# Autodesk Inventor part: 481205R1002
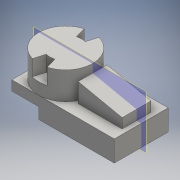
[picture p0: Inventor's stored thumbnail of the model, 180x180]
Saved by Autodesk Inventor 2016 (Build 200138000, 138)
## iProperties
Created: 2018-12
Part Number: 481205R1002
Material: 일반
Document SubType Name: Modeling
Designer: USER
Density: 1 g/cm^3
Appearance: 기본값
Author: USER
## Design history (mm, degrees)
sketch "스케치1"
  geometry: L1 (-78, 41)-(78, 41); L2 (78, 41)-(78, -41); L3 (78, -41)-(-78, -41); L4 (-78, -41)-(-78, 41); L5 (-78, 41)-(78, -41); L6 (78, 41)-(-78, -41); 1 further point
  constraints: 12 end point, 2 midpoint, 2 parallel, 1 horizontal, 1 perpendicular
  dimensions: "d5" = 82 distance of L1.end L2.end; "d6" = 156 distance of L2.end L3.end
extrude "돌출1" new body sketch "스케치1" distance "d7" = 15; taper "d8" = 0 deg
sketch "스케치2"
  geometry: L1 (78, 41)-(-78, 41) reference; L2 (-78, -41)-(78, -41) reference; L3 (-78, 41)-(37, 41); L4 (37, 41)-(37, -41); L5 (37, -41)-(-78, -41); L6 (-78, -41)-(-78, 41); 2 further points
  constraints: 8 end point, 2 parallel, 1 horizontal, 1 horizontal alignment, 1 midpoint, 1 perpendicular, 1 point on line
  dimensions: "d9" = 82 distance of L5.end L1.end (derived); "d10" = 115 distance of L1.end L3.end
extrude "돌출2" join sketch "스케치2" distance "d11" = 17; taper "d12" = 0 deg
node "작업 평면1"
sketch "스케치4"
  geometry: L1 (78, 0)-(-78, 0) reference; L2 (37, -15)-(37, -32) reference; L3 (78, -15)-(37, -15) reference; L4 (37, -15)-(37, 43.573); L5 (78, 0)-(78, 42); L6 (78, 42)-(37, 42); L7 (78, 0)-(37, 0); 1 further point
  constraints: 8 end point, 4 point on line, 2 vertical, 1 perpendicular
  dimensions: "d14" = 41 distance from line of L2 L1.start (derived); "d15" = 82 diameter of L5 L4; "d16" = 42 distance of L5.start L5.end
revolve "회전1" sketch "스케치4" stored, may be unused: angle "d17" = 90 deg
sketch "스케치5"
  geometry: L1 (0, 41)-(0, -41) reference; L2 (6.615, 23.07)-(11.301, 39.412); L3 (-6.615, 23.07)-(-11.301, 39.412); L4 (-58.467, 0)-(58.467, 0); C1 r 41 at (0, 0); C2 r 24 at (0, 0); A1 r 41 centre (0, 0) between (0, 41) and (0, -41) reference; A2 r 41 centre (0, 0) between (11.301, 39.412) and (-11.301, 39.412); A3 r 24 centre (0, 0) between (6.615, 23.07) and (-6.615, 23.07); A4 r 24 centre (0, 0) between (-6.615, -23.07) and (6.615, -23.07); 5 further points
  constraints: 7 point on circle, 6 end point, 5 centre point, 3 coincident, 3 point on line, 2 midpoint, 2 symmetric about line, 1 horizontal, 7 other
  dimensions: "d19" = 16 deg angle of L3 L1; "d20" = 16 deg angle of L2 L1; "d21" = 24 radius of A3; "d22" = 48 diameter of C2
extrude "돌출3" cut sketch "스케치5" distance "d23" = 24; taper "d24" = 0 deg
sketch "스케치6"
  geometry: L1 (48.301, -39.412)-(43.615, -23.07) reference; L2 (30.385, -23.07)-(25.699, -39.412) reference; L3 (25.699, 39.412)-(30.385, 23.07) reference; L4 (43.615, 23.07)-(48.301, 39.412) reference; C1 r 16 at (37, 0); A1 r 24 centre (37, 0) between (30.385, -23.07) and (43.615, -23.07) reference; A2 r 41 centre (37, 0) between (25.699, 39.412) and (25.699, -39.412) reference; A3 r 24 centre (37, 0) between (43.615, 23.07) and (30.385, 23.07) reference; A4 r 41 centre (37, 0) between (48.301, -39.412) and (48.301, 39.412) reference; 1 further point
  constraints: 1 centre point, 1 coincident
  dimensions: "d25" = 32 diameter of C1
extrude "돌출4" cut sketch "스케치6" distance "d26" = 15; taper "d27" = 0 deg
sketch "스케치9"
  geometry: C1 r 22 at (48.923, 0); 1 further point
  constraints: 1 centre point, 1 horizontal alignment
  dimensions: "d31" = 44 diameter of C1
extrude "돌출5" join sketch "스케치9" distance "d32" = 15; taper "d33" = 0 deg
node "작업 평면3"
sketch "스케치8"
  geometry: L1 (37, 0)-(-78, 0) reference; L2 (-48, 29.076)-(-48, -15.681); L3 (-26.923, 15)-(-70.923, 15) reference; L4 (-70.923, 15)-(-4, 29.225); L5 (-4, 42)-(-4, 0) reference; L6 (-70.923, 0)-(-70.923, 15) reference; 1 further point
  constraints: 4 end point, 1 point on line, 1 vertical
  dimensions: "d30" = 30 horizontal distance of L1.end L2.end; "d34" = 78 deg angle of L6 L4
extrude "돌출6" join sketch "스케치8" stored distance "d35" = 44; taper "d36" = 0 deg
node "솔리드1"
mirror "대칭1"
node "투영된 루프1"
other parameters: "d13" = 0, "d18" = 48, "d29" = 0
